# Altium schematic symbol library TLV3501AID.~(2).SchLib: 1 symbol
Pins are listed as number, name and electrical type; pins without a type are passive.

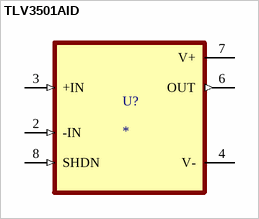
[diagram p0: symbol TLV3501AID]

## TLV3501AID
designator U?
MP: TLV3501AID
footprint SOIC127P599X175-8N
pins: 2 -IN (in), 3 +IN (in), 4 V- (power), 6 OUT (out), 7 V+ (power), 8 SHDN (in)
